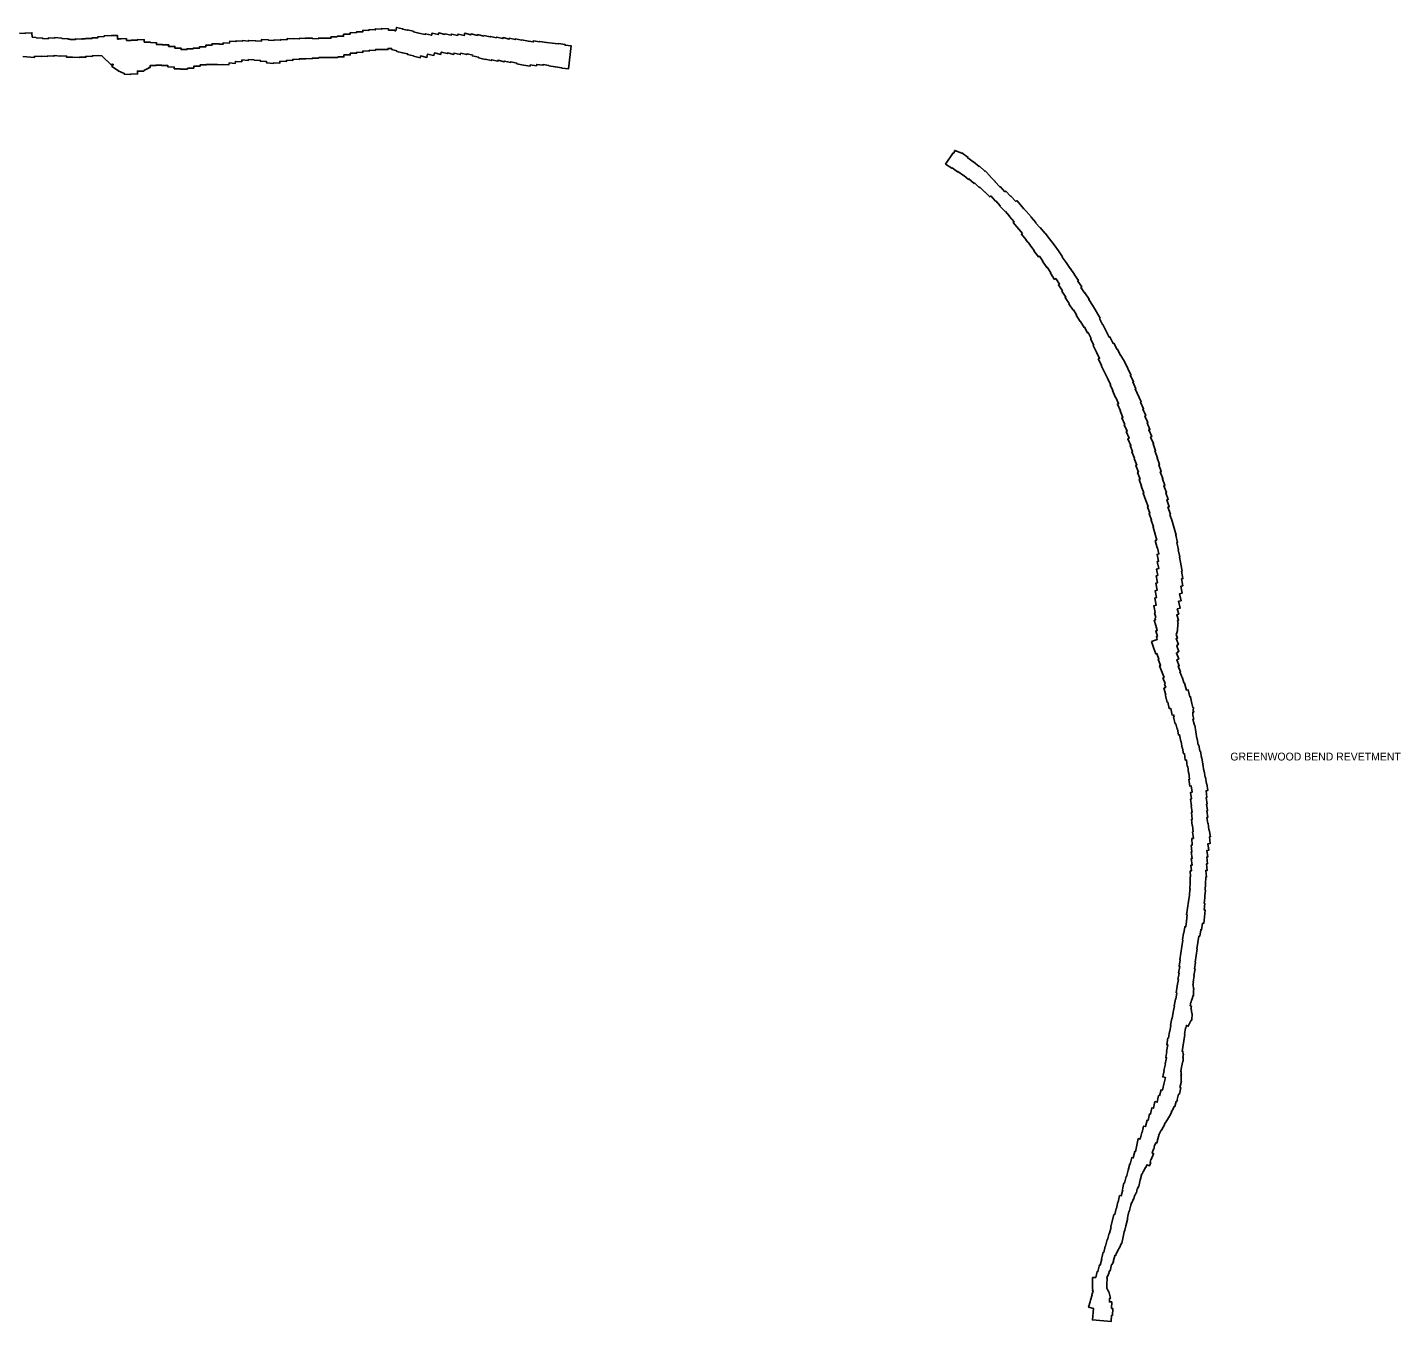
# Model space of a CAD drawing. Extents: x 2650582 to 3923188, y 277893 to 989177.
# Drawn here: x 3200746 to 3228805, y 851258 to 877700 of the extents above; entities that cross this region are included whole.
import ezdxf

# ---------------------------------------------------------------- set-up
doc = ezdxf.new("R2010")
doc.units = 0
doc.layers.add('Level 3', color=7, linetype='Continuous')

msp = doc.modelspace()

# ---------------------------------------------------------------- linework, layer by layer
at = {"layer": 'Level 3'}
for points in [[(3210073, 877536), (3210070, 877524), (3209944, 877553), (3209940, 877538), (3209813, 877568), (3209809, 877551), (3209682, 877581), (3209672, 877538), (3209546, 877565), (3209539, 877537), (3209410, 877566), (3209405, 877543), (3209277, 877571), (3209274, 877558), (3209150, 877588), (3209141, 877553), (3209015, 877583), (3209005, 877541), (3208878, 877570), (3208875, 877556), (3208747, 877585), (3208634, 877611), (3208634, 877621), (3208631, 877621), (3208512, 877649), (3208510, 877642), (3208408, 877666), (3208410, 877672), (3208288, 877700), (3208273, 877632)], [(3200841, 877500), (3200838, 877590), (3200697, 877585), (3200697, 877574), (3200586, 877582)], [(3201571, 877463), (3201571, 877470), (3201451, 877474), (3201451, 877480), (3201303, 877492), (3201302, 877478), (3201171, 877485), (3201170, 877470), (3201053, 877477), (3201054, 877481), (3200921, 877488), (3200921, 877493), (3200841, 877500)], [(3201934, 877466), (3201860, 877470), (3201860, 877460), (3201731, 877466), (3201730, 877455), (3201616, 877457), (3201617, 877461), (3201571, 877463)], [(3202769, 877435), (3202767, 877471), (3202660, 877465), (3202604, 877467), (3202604, 877461), (3202587, 877462), (3202585, 877538), (3202463, 877535), (3202463, 877536), (3202316, 877529), (3202316, 877517), (3202186, 877510), (3202187, 877489), (3202062, 877486), (3202062, 877472), (3201934, 877474), (3201934, 877466)], [(3204007, 877246), (3203886, 877247), (3203887, 877275), (3203760, 877276), (3203760, 877311), (3203631, 877313), (3203632, 877344), (3203505, 877344), (3203506, 877349), (3203385, 877351), (3203386, 877389), (3203262, 877392), (3203262, 877398), (3203132, 877400), (3203133, 877449), (3202994, 877453), (3202992, 877439), (3202866, 877441), (3202865, 877432), (3202769, 877435)], [(3206050, 877446), (3205918, 877453), (3205917, 877437), (3205788, 877448), (3205787, 877436), (3205669, 877443), (3205670, 877447), (3205530, 877455), (3205527, 877419), (3205409, 877426), (3205409, 877428), (3205269, 877436), (3205269, 877422), (3205139, 877430), (3205138, 877418), (3205008, 877426), (3205007, 877410), (3204878, 877418), (3204876, 877381), (3204747, 877388), (3204744, 877356), (3204660, 877361), (3204660, 877366), (3204520, 877367), (3204520, 877338), (3204391, 877338), (3204391, 877305), (3204263, 877307), (3204263, 877278), (3204133, 877278), (3204134, 877264), (3204008, 877265), (3204007, 877246)], [(3207075, 877506), (3206947, 877506), (3206947, 877479), (3206817, 877481), (3206817, 877479), (3206689, 877480), (3206689, 877470), (3206566, 877472), (3206566, 877483), (3206425, 877482), (3206425, 877477), (3206300, 877480), (3206300, 877466), (3206175, 877472), (3206175, 877466), (3206052, 877474), (3206050, 877446)], [(3208273, 877632), (3208253, 877632), (3208253, 877642), (3208125, 877643), (3208126, 877671), (3207985, 877676), (3207984, 877668), (3207854, 877675), (3207853, 877650), (3207726, 877657), (3207725, 877639), (3207600, 877643), (3207599, 877610), (3207470, 877612), (3207469, 877593), (3207341, 877596), (3207340, 877560), (3207205, 877561), (3207205, 877519), (3207075, 877520), (3207075, 877506)], [(3210100, 877051), (3210228, 877023), (3210232, 877039), (3210359, 877010), (3210363, 877030), (3210490, 877000), (3210493, 877014), (3210620, 876985), (3210623, 876995), (3210747, 876970), (3210745, 876958), (3210881, 876931), (3211017, 876912), (3211021, 876936), (3211147, 876918), (3211152, 876946), (3211280, 876928), (3211282, 876940), (3211398, 876924), (3211398, 876917), (3211531, 876897), (3211531, 876896), (3211665, 876878), (3211664, 876871), (3211803, 876857), (3211858, 877323), (3211731, 877337), (3211733, 877353), (3211595, 877370), (3211594, 877363), (3211468, 877380), (3211467, 877376), (3211351, 877393), (3211351, 877394), (3211213, 877414), (3211212, 877408), (3211084, 877425), (3211081, 877406), (3210982, 877419), (3210982, 877420), (3210845, 877446), (3210844, 877441), (3210716, 877466), (3210713, 877453), (3210596, 877480), (3210592, 877462), (3210466, 877492), (3210461, 877472), (3210333, 877502), (3210330, 877488), (3210205, 877518), (3210202, 877506), (3210073, 877536)], [(3207086, 877099), (3207212, 877098), (3207213, 877140), (3207341, 877139), (3207341, 877174), (3207471, 877173), (3207471, 877193), (3207600, 877189), (3207601, 877220), (3207729, 877217), (3207729, 877233), (3207856, 877230), (3207856, 877248), (3207984, 877246), (3207984, 877251), (3208113, 877249), (3208113, 877269), (3208188, 877270), (3208182, 877247)], [(3208182, 877247), (3208294, 877222), (3208292, 877210), (3208412, 877183), (3208412, 877184), (3208513, 877161), (3208510, 877148), (3208637, 877118), (3208636, 877114), (3208773, 877082), (3208781, 877117), (3208908, 877087), (3208924, 877157), (3209051, 877128), (3209063, 877179), (3209190, 877150), (3209201, 877195), (3209327, 877167), (3209329, 877178), (3209457, 877149), (3209463, 877175), (3209591, 877147), (3209597, 877174), (3209724, 877145), (3209728, 877164), (3209844, 877136), (3209840, 877119), (3209966, 877090), (3209964, 877081), (3210099, 877048), (3210100, 877051)], [(3200650, 877107), (3200890, 877089), (3200892, 877110), (3201033, 877103), (3201034, 877114), (3201160, 877107), (3201160, 877117), (3201288, 877110), (3201289, 877125), (3201422, 877115), (3201422, 877119), (3201544, 877114), (3201543, 877096), (3201660, 877093), (3201660, 877090), (3201810, 877083), (3201811, 877095), (3201940, 877090), (3201941, 877110), (3202072, 877108), (3202072, 877123), (3202204, 877127)], [(3202204, 877127), (3202204, 877125), (3202267, 877121), (3202365, 877021), (3202368, 877024), (3202452, 876942), (3202464, 876932), (3202486, 876956), (3202500, 876945), (3202471, 876904), (3202589, 876824), (3202591, 876827), (3202591, 876821), (3202601, 876821), (3202598, 876814), (3202722, 876760), (3202722, 876747), (3202860, 876741), (3202860, 876749), (3202992, 876746), (3202993, 876807), (3203121, 876805), (3203121, 876817), (3203231, 876878), (3203229, 876882), (3203251, 876881), (3203252, 876922), (3203375, 876920), (3203375, 876930), (3203490, 876929), (3203491, 876922), (3203617, 876920), (3203617, 876893), (3203746, 876891), (3203745, 876855), (3203875, 876854), (3203875, 876850), (3204016, 876848), (3204017, 876866)], [(3204017, 876866), (3204145, 876869), (3204145, 876908), (3204273, 876907), (3204272, 876936), (3204403, 876936), (3204403, 876944), (3204532, 876942), (3204532, 876945), (3204627, 876944), (3204732, 876939), (3204733, 876945), (3204863, 876937), (3204865, 876974), (3204993, 876966), (3204995, 877007), (3205125, 877000), (3205127, 877037), (3205256, 877028), (3205257, 877043), (3205377, 877036), (3205377, 877034), (3205506, 877028), (3205505, 877010), (3205634, 877002), (3205633, 876975), (3205774, 876964), (3205775, 876977), (3205902, 876970), (3205904, 877009), (3206036, 877001), (3206038, 877029)], [(3206038, 877029), (3206168, 877023), (3206169, 877051), (3206301, 877046), (3206301, 877060), (3206433, 877057), (3206433, 877063), (3206564, 877062), (3206565, 877074), (3206697, 877074), (3206698, 877085), (3206957, 877083), (3206957, 877086), (3207086, 877085), (3207086, 877099)], [(3219660, 875141), (3219676, 875133), (3219695, 875186), (3219840, 875132), (3219842, 875135), (3219967, 875042), (3219962, 875035), (3220074, 874952), (3220079, 874956), (3220193, 874858), (3220200, 874864), (3220310, 874763), (3220315, 874767), (3220425, 874656), (3220421, 874653), (3220523, 874549), (3220519, 874545), (3220614, 874442), (3220623, 874449), (3220721, 874342), (3220738, 874358), (3220837, 874251), (3220843, 874255), (3220944, 874146), (3220963, 874162), (3221108, 873996), (3221154, 873943), (3221156, 873946), (3221260, 873828), (3221258, 873826), (3221353, 873716), (3221348, 873710), (3221438, 873608), (3221440, 873610), (3221538, 873496), (3221542, 873499), (3221631, 873383), (3221633, 873384), (3221727, 873261), (3221815, 873137), (3221814, 873136), (3221897, 873011), (3221893, 873009), (3221969, 872895), (3221971, 872896), (3222053, 872775), (3222057, 872778), (3222143, 872649), (3222141, 872647), (3222223, 872527), (3222209, 872518), (3222291, 872397), (3222275, 872386), (3222352, 872272), (3222357, 872276), (3222443, 872146), (3222432, 872138), (3222510, 872022), (3222512, 872023), (3222592, 871888), (3222590, 871887), (3222665, 871762), (3222654, 871756)], [(3222628, 870927), (3222655, 870940), (3222593, 871061), (3222594, 871063), (3222523, 871202), (3222536, 871209), (3222470, 871338), (3222482, 871345), (3222419, 871467), (3222407, 871460), (3222350, 871574), (3222342, 871568), (3222267, 871692), (3222260, 871689), (3222179, 871823), (3222186, 871828), (3222120, 871928), (3222117, 871926), (3222030, 872055), (3222033, 872058), (3221951, 872179), (3221968, 872189), (3221885, 872311), (3221895, 872319), (3221813, 872440), (3221836, 872455), (3221761, 872567), (3221737, 872550), (3221650, 872680), (3221660, 872687), (3221584, 872800), (3221576, 872795), (3221489, 872923), (3221492, 872926), (3221424, 873024), (3221407, 873010), (3221310, 873135), (3221319, 873140), (3221229, 873256), (3221235, 873260), (3221149, 873359), (3221153, 873362), (3221058, 873474), (3221079, 873491), (3220889, 873713), (3220907, 873729), (3220812, 873839), (3220817, 873843), (3220732, 873942), (3220726, 873936), (3220620, 874050), (3220626, 874056), (3220534, 874155), (3220530, 874150), (3220430, 874257), (3220409, 874236), (3220312, 874339), (3220309, 874335), (3220206, 874439), (3220195, 874429), (3220100, 874523), (3220089, 874511), (3219986, 874605), (3219978, 874596), (3219881, 874677), (3219877, 874672), (3219759, 874758), (3219753, 874748), (3219641, 874829), (3219637, 874822), (3219507, 874908), (3219660, 875141)], [(3222654, 871756), (3222718, 871629), (3222721, 871631), (3222854, 871369), (3222865, 871375), (3222931, 871244), (3222944, 871252), (3223011, 871121), (3223018, 871125), (3223084, 870994), (3223092, 870999), (3223162, 870872), (3223232, 870733), (3223230, 870732), (3223295, 870601), (3223283, 870595), (3223349, 870465), (3223334, 870457), (3223393, 870318), (3223385, 870315), (3223504, 870048), (3223492, 870042), (3223553, 869907), (3223541, 869901), (3223600, 869768), (3223582, 869759), (3223640, 869625), (3223626, 869619), (3223685, 869484), (3223661, 869475), (3223721, 869341), (3223698, 869330), (3223757, 869196), (3223747, 869192), (3223800, 869051), (3223786, 869046), (3223838, 868909), (3223830, 868906), (3223882, 868771), (3223864, 868763), (3223916, 868627), (3223896, 868619), (3223948, 868483), (3223939, 868479), (3223990, 868342), (3223971, 868336), (3224023, 868199), (3224006, 868192), (3224057, 868056), (3224028, 868045), (3224079, 867908), (3224053, 867898), (3224101, 867755), (3224093, 867751), (3224140, 867614), (3224138, 867613), (3224222, 867329), (3224212, 867326), (3224250, 867179), (3224232, 867175), (3224268, 867029), (3224262, 867028), (3224296, 866881), (3224286, 866878), (3224318, 866737), (3224314, 866736), (3224346, 866593), (3224330, 866590), (3224358, 866440), (3224330, 866435), (3224358, 866293), (3224315, 866283), (3224342, 866140), (3224291, 866130), (3224319, 865986), (3224271, 865977), (3224300, 865832), (3224242, 865822), (3224272, 865711), (3224231, 865701), (3224268, 865590), (3224247, 865583)], [(3223807, 865480), (3223772, 865586), (3223801, 865597), (3223788, 865629), (3223804, 865646), (3223778, 865742), (3223788, 865745), (3223762, 865885), (3223813, 865896), (3223785, 866040), (3223817, 866049), (3223791, 866191), (3223830, 866199), (3223803, 866342), (3223838, 866351), (3223811, 866494), (3223845, 866502), (3223816, 866631), (3223865, 866643), (3223833, 866785), (3223861, 866792), (3223829, 866933), (3223869, 866942), (3223838, 867069), (3223835, 867068), (3223794, 867219), (3223823, 867227), (3223747, 867490), (3223756, 867493), (3223708, 867631), (3223713, 867633), (3223666, 867770), (3223685, 867777), (3223635, 867905), (3223650, 867911), (3223602, 868037), (3223599, 868035), (3223543, 868183), (3223557, 868188), (3223506, 868324), (3223515, 868327), (3223462, 868464), (3223483, 868472), (3223430, 868609), (3223447, 868616), (3223395, 868752), (3223414, 868758), (3223363, 868894), (3223367, 868896), (3223315, 869031), (3223330, 869038), (3223279, 869155), (3223294, 869161), (3223233, 869296), (3223259, 869306), (3223200, 869442), (3223218, 869449), (3223158, 869582), (3223172, 869589), (3223113, 869724), (3223133, 869733), (3223074, 869866), (3223080, 869869), (3223020, 870004), (3223043, 870014), (3222988, 870139), (3222982, 870138), (3222920, 870280), (3222928, 870283), (3222869, 870397), (3222880, 870402), (3222814, 870532), (3222820, 870535), (3222690, 870795), (3222695, 870797), (3222628, 870927)], [(3223715, 865153), (3223834, 865197), (3223817, 865251), (3223836, 865257), (3223804, 865368), (3223835, 865377), (3223804, 865480), (3223807, 865480)], [(3224247, 865583), (3224259, 865521), (3224252, 865519), (3224254, 865509), (3224257, 865507), (3224248, 865376), (3224245, 865375), (3224233, 865330), (3224223, 865295)], [(3223968, 864205), (3224006, 864214), (3223982, 864283), (3223995, 864292), (3223950, 864409), (3223972, 864418), (3223882, 864658), (3223900, 864665), (3223854, 864789), (3223869, 864794), (3223827, 864906), (3223807, 864900), (3223765, 865009), (3223759, 865032), (3223715, 865153)], [(3224223, 865295), (3224248, 865223), (3224219, 865213), (3224266, 865090), (3224237, 865079), (3224243, 865064), (3224234, 865061), (3224275, 864951), (3224250, 864943), (3224255, 864929), (3224225, 864918), (3224273, 864796), (3224237, 864781), (3224282, 864659), (3224262, 864651), (3224308, 864535), (3224297, 864530), (3224327, 864451), (3224338, 864421), (3224342, 864423), (3224378, 864314), (3224382, 864303), (3224389, 864304)], [(3224389, 864304), (3224429, 864160), (3224463, 864168), (3224499, 864022), (3224514, 864025), (3224540, 863887), (3224551, 863832)], [(3224166, 863655), (3224136, 863650), (3224111, 863787), (3224079, 863781), (3224050, 863912), (3224037, 863909), (3224001, 864053), (3224008, 864055), (3223968, 864205)], [(3224551, 863832), (3224564, 863803), (3224573, 863802), (3224570, 863745), (3224580, 863709), (3224558, 863704), (3224559, 863650), (3224578, 863568), (3224563, 863564), (3224595, 863441), (3224601, 863441), (3224621, 863308), (3224624, 863308), (3224645, 863173), (3224649, 863174), (3224673, 863038), (3224682, 863040), (3224706, 862911), (3224719, 862912), (3224739, 862777), (3224745, 862777), (3224764, 862644), (3224768, 862644), (3224785, 862509), (3224793, 862510), (3224811, 862377), (3224821, 862378), (3224838, 862246), (3224845, 862245), (3224866, 862106), (3224831, 862102), (3224847, 861966), (3224835, 861966), (3224853, 861832), (3224843, 861831), (3224861, 861697), (3224849, 861696), (3224866, 861559), (3224849, 861558), (3224866, 861437)], [(3224547, 861391), (3224534, 861520), (3224549, 861522), (3224531, 861660), (3224544, 861662), (3224527, 861797), (3224533, 861798), (3224514, 861934), (3224531, 861936), (3224515, 862069), (3224544, 862073), (3224527, 862202), (3224499, 862199), (3224482, 862338), (3224494, 862340), (3224479, 862468), (3224472, 862468), (3224456, 862601), (3224447, 862600), (3224431, 862734), (3224407, 862731), (3224390, 862864), (3224371, 862861), (3224351, 862975), (3224344, 862976), (3224321, 863112), (3224315, 863111), (3224291, 863246), (3224271, 863242), (3224250, 863367), (3224239, 863365), (3224213, 863472), (3224200, 863470), (3224164, 863607), (3224177, 863610), (3224166, 863655)], [(3224866, 861437), (3224873, 861438), (3224889, 861302), (3224897, 861304), (3224920, 861162), (3224900, 861159), (3224918, 861028), (3224870, 861022), (3224887, 860888), (3224849, 860884), (3224867, 860750), (3224844, 860748), (3224861, 860612), (3224839, 860610), (3224855, 860477), (3224826, 860474), (3224839, 860340), (3224826, 860339), (3224822, 860201), (3224820, 860201), (3224814, 860071), (3224822, 860071), (3224808, 859956), (3224806, 859914), (3224793, 859802), (3224807, 859798), (3224795, 859669), (3224814, 859666), (3224783, 859393), (3224758, 859396), (3224741, 859261), (3224723, 859263), (3224701, 859129), (3224686, 859133), (3224662, 859006), (3224666, 859005), (3224643, 858872), (3224651, 858870), (3224607, 858600)], [(3224313, 858787), (3224315, 858788), (3224338, 858918), (3224335, 858920), (3224355, 859053), (3224350, 859055), (3224373, 859193), (3224375, 859193), (3224397, 859325), (3224415, 859321), (3224428, 859441), (3224431, 859440), (3224447, 859567), (3224433, 859569), (3224450, 859704), (3224454, 859703), (3224470, 859840), (3224473, 859839), (3224490, 859967), (3224492, 860004), (3224504, 860098), (3224498, 860099), (3224505, 860224), (3224507, 860224), (3224509, 860345), (3224515, 860345), (3224509, 860464), (3224533, 860464), (3224519, 860580), (3224544, 860580), (3224528, 860716), (3224545, 860717), (3224528, 860853), (3224543, 860854), (3224528, 860989), (3224550, 860992), (3224537, 861125), (3224574, 861128), (3224557, 861264), (3224566, 861265), (3224552, 861392), (3224547, 861391)], [(3223880, 855871), (3223912, 855995), (3223943, 855987), (3223970, 856110), (3223968, 856111), (3224000, 856245), (3223946, 856257), (3223977, 856387), (3223968, 856390), (3224001, 856523), (3223997, 856524), (3224025, 856647), (3224006, 856651), (3224029, 856775), (3224025, 856776), (3224050, 856909), (3224027, 856913), (3224051, 857052), (3224063, 857049), (3224086, 857183), (3224090, 857182), (3224110, 857311), (3224106, 857313), (3224131, 857450), (3224136, 857449), (3224158, 857580), (3224161, 857579), (3224184, 857708), (3224179, 857709), (3224204, 857848), (3224211, 857847), (3224232, 857974), (3224223, 857976), (3224243, 858113), (3224240, 858114), (3224265, 858246), (3224257, 858247), (3224279, 858377), (3224268, 858381), (3224293, 858513), (3224278, 858516), (3224299, 858651), (3224292, 858651), (3224313, 858787)], [(3224607, 858600), (3224614, 858600), (3224594, 858465), (3224605, 858462), (3224583, 858329), (3224590, 858327), (3224565, 858195), (3224575, 858193), (3224564, 858137), (3224569, 858138), (3224571, 858056), (3224582, 858058), (3224572, 858018), (3224577, 858019), (3224575, 857916), (3224565, 857917), (3224540, 857830), (3224535, 857831), (3224525, 857786), (3224521, 857786), (3224506, 857709), (3224532, 857705), (3224521, 857650), (3224529, 857651), (3224541, 857554), (3224545, 857554), (3224537, 857415), (3224526, 857415), (3224467, 857290), (3224430, 857309), (3224420, 857254), (3224410, 857255), (3224388, 857130), (3224397, 857126), (3224353, 856861), (3224359, 856861), (3224346, 856777), (3224358, 856778), (3224361, 856721), (3224367, 856720), (3224355, 856650), (3224362, 856651), (3224361, 856581), (3224356, 856581), (3224328, 856455), (3224332, 856453), (3224313, 856364), (3224324, 856362), (3224324, 856315), (3224328, 856313), (3224317, 856272), (3224322, 856274), (3224320, 856175), (3224326, 856172), (3224298, 856041), (3224315, 856037), (3224287, 855904), (3224268, 855907), (3224243, 855792)], [(3222949, 853445), (3222966, 853442), (3222995, 853570), (3223004, 853569), (3223030, 853701), (3223034, 853700), (3223063, 853833), (3223098, 853825), (3223127, 853952), (3223124, 853953), (3223154, 854089), (3223166, 854087), (3223197, 854220), (3223207, 854216), (3223237, 854349), (3223241, 854348), (3223270, 854478), (3223283, 854476), (3223312, 854607), (3223342, 854602), (3223373, 854733), (3223390, 854728), (3223446, 854996), (3223487, 854985), (3223517, 855118), (3223522, 855118), (3223552, 855249), (3223594, 855240), (3223625, 855371), (3223646, 855367), (3223676, 855500), (3223695, 855494), (3223723, 855626), (3223756, 855617), (3223785, 855752), (3223832, 855739), (3223862, 855876), (3223880, 855871)], [(3224243, 855792), (3224246, 855790), (3224225, 855748), (3224218, 855753), (3224196, 855654), (3224185, 855657), (3224134, 855558), (3224128, 855562), (3224122, 855531), (3224081, 855454), (3224062, 855417), (3224006, 855330), (3223984, 855296), (3223986, 855293), (3223918, 855170), (3223915, 855169), (3223871, 855085), (3223860, 855038), (3223856, 855038), (3223827, 854906), (3223806, 854910), (3223779, 854850), (3223776, 854852), (3223761, 854781), (3223757, 854783), (3223727, 854702), (3223758, 854685), (3223711, 854569), (3223704, 854572), (3223688, 854512), (3223700, 854506), (3223673, 854440), (3223619, 854459), (3223597, 854408), (3223592, 854410), (3223590, 854405), (3223596, 854402), (3223547, 854314), (3223539, 854320), (3223529, 854277), (3223519, 854277), (3223487, 854147), (3223483, 854150), (3223455, 854017), (3223451, 854018), (3223431, 853968), (3223426, 853971), (3223409, 853887), (3223402, 853889), (3223365, 853805), (3223354, 853761), (3223348, 853763), (3223315, 853681), (3223309, 853683), (3223297, 853633), (3223292, 853634), (3223262, 853502), (3223250, 853505), (3223223, 853375), (3223230, 853373)], [(3222580, 852155), (3222607, 852283), (3222621, 852280), (3222651, 852414), (3222669, 852409), (3222699, 852534), (3222693, 852535), (3222727, 852672), (3222739, 852669), (3222771, 852801), (3222777, 852800), (3222809, 852931), (3222817, 852930), (3222849, 853062), (3222860, 853061), (3222891, 853189), (3222888, 853190), (3222949, 853445)], [(3223230, 853373), (3223189, 853213), (3223169, 853123), (3223160, 853088), (3223139, 852989), (3223134, 852990), (3223110, 852857), (3223105, 852859), (3223055, 852752), (3223050, 852755), (3223044, 852730), (3223039, 852731), (3223002, 852652), (3222995, 852657), (3222985, 852605), (3222966, 852609), (3222957, 852571), (3222935, 852483), (3222941, 852480), (3222921, 852442), (3222909, 852418), (3222900, 852424), (3222887, 852354), (3222875, 852318), (3222864, 852290), (3222855, 852293), (3222840, 852224), (3222837, 852223), (3222814, 852175), (3222809, 852179), (3222802, 852147)], [(3222802, 852147), (3222811, 852147), (3222806, 852023), (3222804, 852023), (3222801, 851941), (3222837, 851869), (3222844, 851871), (3222875, 851734), (3222859, 851730), (3222856, 851660), (3222904, 851659), (3222899, 851526), (3222928, 851524), (3222916, 851384), (3222900, 851386), (3222889, 851258), (3222508, 851291), (3222528, 851526), (3222431, 851551), (3222461, 851663), (3222472, 851693), (3222502, 851803), (3222497, 851804), (3222522, 851887), (3222509, 851891), (3222517, 851921), (3222508, 851921), (3222512, 852034), (3222509, 852034), (3222513, 852158)], [(3222513, 852158), (3222580, 852155)]]:
    msp.add_lwpolyline(points, dxfattribs=at)

# ---------------------------------------------------------------- texts
msp.add_text('GREENWOOD BEND REVETMENT', height=160, dxfattribs=at).set_placement((3225327, 862722))

doc.saveas('drawing.dxf')
